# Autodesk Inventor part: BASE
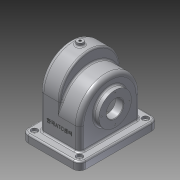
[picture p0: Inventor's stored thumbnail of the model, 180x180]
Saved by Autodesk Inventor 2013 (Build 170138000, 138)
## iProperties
Created: 2017-11
Part Number: BASE
Material: 알루미늄 6061
Document SubType Name: Modeling
Designer: Administrator
Density: 2.71 g/cm^3
Mass: 1097.64 g
Surface Area: 1194.15 cm^2
Volume: 405.032 cm^3
Author: Administrator
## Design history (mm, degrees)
sketch "스케치1"
  geometry: L1 (-58, 0)-(-58, -65); L2 (-58, -65)-(58, -65); L3 (58, -65)-(58, 0); A1 r 58 centre (0, 0) between (58, 0) and (-58, 0); 1 further point
  constraints: 6 end point, 2 point on circle, 2 tangent, 1 centre point, 1 coincident, 1 perpendicular, 1 vertical, 1 vertical alignment
  dimensions: "d0" = 116 diameter of A1; "d3" = 65 distance of L1.start L1.end
extrude "돌출1" new body sketch "스케치1" distance "d4" = 38; taper "d5" = 0 deg
sketch "스케치2"
  geometry: L1 (0, 58)-(65, 58) reference; L2 (65, 58)-(65, -58) reference; L3 (65, -58)-(0, -58) reference; L4 (65, -58)-(65, 58); L5 (65, 58)-(23, 58); L6 (55.666, -58)-(23, -58); L7 (55.666, -58)-(65, -58); A1 r 58 centre (0, 0) between (0, 58) and (0, -58) reference; A2 r 58 centre (23, 0) between (23, 58) and (23, -58); 1 further point
  constraints: 8 end point, 2 collinear, 2 point on circle, 2 tangent, 1 centre point, 1 horizontal alignment, 1 point on line, 1 vertical alignment
  dimensions: "d6" = 116 diameter of A2; "d8" = 42 distance from line of L2 A2.centre
extrude "돌출2" join sketch "스케치2" distance "d9" = 38; taper "d10" = 0 deg
feature "쉘1" dims "d11" = 5
sketch "스케치4"
  geometry: L1 (-71, 111)-(-71, 5) reference; L2 (-71, 5)-(-5, 5) reference; L3 (-5, 5)-(-5, 111) reference; L4 (-5, 111)-(-71, 111) reference; L5 (-76, 0)-(-76, 116) reference; L6 (-76, 116)-(0, 116) reference; L7 (0, 116)-(0, 0) reference; L8 (0, 0)-(-76, 0) reference; L9 (17, 133)-(-93, 133); L10 (-93, 133)-(-93, -17); L11 (-93, -17)-(17, -17); L12 (17, -17)-(17, 133); 1 further point
  constraints: 8 end point, 3 other
  dimensions: "d12" = 110 distance of L9.start L9.end; "d14" = 150 distance of L9.end L10.end (derived)
extrude "돌출3" join sketch "스케치4" distance "d15" = 15; taper "d16" = 0 deg
fillet "모깎기1" dims "d17" = 12
sketch "스케치7"
  geometry: L1 (-80, 75)-(-65, 75) reference; L2 (-65, 75)-(-65, 58) reference; L3 (-65, 58)-(-65, -58) reference; L4 (-65, -58)-(-65, -75) reference; L5 (-65, -75)-(-80, -75) reference; L6 (-80, -75)-(-80, 75) reference; L7 (-65, 58)-(0, 58) reference; L8 (0, -58)-(-65, -58) reference; C1 r 37.5 at (-15, 0); A1 r 58 centre (0, 0) between (0, -58) and (0, 58) reference; 1 further point
  constraints: 1 centre point, 1 horizontal alignment
  dimensions: "d18" = 75 diameter of C1; "d20" = 65 distance from line of L6 C1.centre
extrude "돌출4" join sketch "스케치7" distance "d21" = 9; taper "d22" = 0 deg
sketch "스케치8"
  geometry: L1 (23, 58)-(65, 58) reference; L2 (65, 58)-(65, 75) reference; L3 (65, 75)-(80, 75) reference; L4 (80, 75)-(80, -75) reference; L5 (80, -75)-(65, -75) reference; L6 (65, -75)-(65, -58) reference; L7 (65, -58)-(65, 58) reference; L8 (65, -58)-(23, -58) reference; C1 r 31 at (15, 0); A1 r 58 centre (23, 0) between (23, 58) and (23, -58) reference; 1 further point
  constraints: 1 centre point, 1 horizontal alignment
  dimensions: "d23" = 62 diameter of C1; "d25" = 65 distance from line of L4 C1.centre
extrude "돌출5" join sketch "스케치8" distance "d26" = 10; taper "d27" = 0 deg
sketch "스케치9"
  geometry: L1 (50, -73.909)-(50, 73.909) reference; L2 (50, 73.909)-(65, 73.909) reference; L3 (65, 73.909)-(65, -73.909) reference; L4 (65, -73.909)-(50, -73.909) reference; C1 r 31 at (0, 0) reference; C2 r 16 at (0, 0); 1 further point
  constraints: 1 centre point, 1 coincident
  dimensions: "d28" = 32 diameter of C2
extrude "돌출6" cut sketch "스케치9" stored distance "d30" = 10; taper "d31" = 0 deg
chamfer "모따기1" distance "d32" = 1; stored, may be unused: second distance "d33" = 2, angle "d34" = 45 deg
fillet "모깎기2" dims "d35" = 3
fillet "모깎기3" dims "d36" = 3
hole "구멍1" diameter "d39" = 5; stored, may be unused: countersink angle "d43" = 90 deg, drill point angle "d45" = 118 deg; dims "d37" = 10, "d38" = 10, "d40" = 6, "d41" = 12, "d42" = 5, "d44" = 8
node "작업 평면1"
sketch "스케치11"
  geometry: L1 (55, -66.317)-(55, -59.683) reference; L2 (55, -59.683)-(50, -59.683) reference; L3 (50, -59.683)-(50, 59.683) reference; L4 (50, 59.683)-(55, 59.683) reference; L5 (55, 59.683)-(55, 66.317) reference; L6 (55, 66.317)-(50, 66.317) reference; L7 (50, 66.317)-(50, 73.909) reference; L8 (50, 73.909)-(65, 73.909) reference; L9 (65, 73.909)-(65, -73.909) reference; L10 (65, -73.909)-(50, -73.909) reference; L11 (50, -73.909)-(50, -66.317) reference; L12 (50, -66.317)-(55, -66.317) reference; C1 r 31 at (0, 0) reference; C2 r 17 at (0, 0) reference; C3 r 26 at (0, 0); 2 further points
  constraints: 1 centre point, 1 coincident, 1 horizontal alignment
  dimensions: "d46" = 52 diameter of C3; "d48" = 26 distance of C1.centre point (-26, 0)
hole "구멍2" sketch "스케치11" at (-26, 0) diameter "d49" = 2.459; stored, may be unused: countersink angle "d53" = 90 deg, drill point angle "d55" = 118 deg; dims "d50" = 6, "d51" = 12, "d52" = 5, "d54" = 8
sketch "스케치12"
  geometry: L1 (-65, 74.314)-(-50, 74.314) reference; L2 (-50, 74.314)-(-50, 67.472) reference; L3 (-50, 67.472)-(-55, 67.472) reference; L4 (-55, 67.472)-(-55, 58.528) reference; L5 (-55, 58.528)-(-50, 58.528) reference; L6 (-50, 58.528)-(-50, -58.528) reference; L7 (-50, -58.528)-(-55, -58.528) reference; L8 (-55, -58.528)-(-55, -67.472) reference; L9 (-55, -67.472)-(-50, -67.472) reference; L10 (-50, -67.472)-(-50, -74.314) reference; L11 (-50, -74.314)-(-65, -74.314) reference; L12 (-65, -74.314)-(-65, 74.314) reference; C1 r 37.5 at (0, 0) reference; C2 r 17 at (0, 0) reference; 2 further points
  constraints: 1 horizontal alignment
  dimensions: "d59" = 29 distance of point (29, 0) C1.centre
hole "구멍3" sketch "스케치12" at (29, 0) diameter "d60" = 2.459; stored, may be unused: countersink angle "d64" = 90 deg, drill point angle "d66" = 118 deg; dims "d61" = 6, "d62" = 12, "d63" = 5, "d65" = 8
fillet "모깎기4" dims "d70" = 3
node "작업 평면2"
sketch "스케치13"
  geometry: L1 (0, 0)-(35, 0) reference; L2 (35, 116)-(35, 0) reference; L3 (0, 116)-(35, 116) reference; L4 (35, 116)-(76, 116) reference; L5 (41, 5.819)-(41, 110.181) reference; L6 (35, 0)-(76, 0) reference; L7 (-9, 95.5)-(-9, 20.5) reference; L8 (86, 27)-(86, 89) reference; L9 (0, 3)-(0, 113) reference; L10 (0, 0)-(0, 116) reference; L11 (76, 116)-(76, 0) reference; C1 r 6 at (19, 58); 4 further points
  constraints: 1 centre point, 1 horizontal alignment, 1 midpoint, 4 other
  dimensions: "d74" = 19 distance from line of C1.centre L9; "d75" = 12 diameter of C1
extrude "돌출7" join sketch "스케치13" stored distance "d76" = 10; taper "d77" = 0 deg
fillet "모깎기6" dims "d78" = 3
hole "구멍4" diameter "d81" = 4.459; stored, may be unused: countersink angle "d85" = 90 deg, drill point angle "d87" = 118 deg; dims "d79" = 10, "d80" = 10, "d82" = 6, "d83" = 12, "d84" = 5, "d86" = 8
sketch "스케치15"
  geometry: L1 (42.683, -47)-(49.317, -47) reference; L2 (49.317, -47)-(49.317, -42) reference; L3 (49.317, -42)-(55, -42) reference; L4 (58, -45)-(58, -57) reference; L5 (58, -57)-(-52, -57) reference; L6 (-52, -57)-(-52, -45) reference; L7 (-49, -42)-(-43.317, -42) reference; L8 (-43.317, -42)-(-43.317, -47) reference; L9 (-43.317, -47)-(-36.683, -47) reference; L10 (-36.683, -47)-(-36.683, -42) reference; L11 (42.683, -42)-(42.683, -47) reference; L12 (-35, 23)-(0, 23) reference; L13 (0, 23)-(0, 0) reference; L14 (0, 0)-(41, 0) reference; L15 (-21.887, -13.398)-(27.887, -13.398); L16 (27.887, -13.398)-(27.887, -20.602); L17 (27.887, -20.602)-(-21.887, -20.602); L18 (-21.887, -20.602)-(-21.887, -13.398); L19 (-35, -42)-(-35, 23) reference; L20 (-36.683, -42)-(-35, -42) reference; L21 (-35, -42)-(41, -42) reference; L22 (41, -42)-(42.683, -42) reference; L23 (41, 0)-(41, -42) reference; A1 r 3 centre (55, -45) between (58, -45) and (55, -42) reference; A2 r 3 centre (-49, -45) between (-49, -42) and (-52, -45) reference; 2 further points
  constraints: 2 midpoint, 2 other
  dimensions: "d88" = 3.60244 distance of point (-21.887, -17) L15.start; "d90" = 7.20489 distance between parallel lines of L17 L15 (derived); "d91" = 49.77477 distance of L15.start L15.end
feature "엠보싱1" sketch "스케치15" dims "d0" = 116, "d3" = 65, "d94" = 0.5, "d95" = 0
fillet "모깎기7" dims "d96" = 8
fillet "모깎기8" dims "d97" = 3
node "솔리드1"
mirror "대칭1"
mirror "대칭2"
pattern_circular "원형 패턴1" dims angle "d57" = 360 deg
pattern_circular "원형 패턴2" dims angle "d68" = 360 deg
node "투영된 루프1"
node "투영된 루프2"
node "절단 모서리 투영1"
node "절단 모서리 투영2"
node "절단 모서리 투영4"
node "절단 모서리 투영5"
node "절단 모서리 투영6"
node "절단 모서리 투영7"
node "절단 모서리 투영8"
node "절단 모서리 투영9"
other parameters: "d72" = -144
